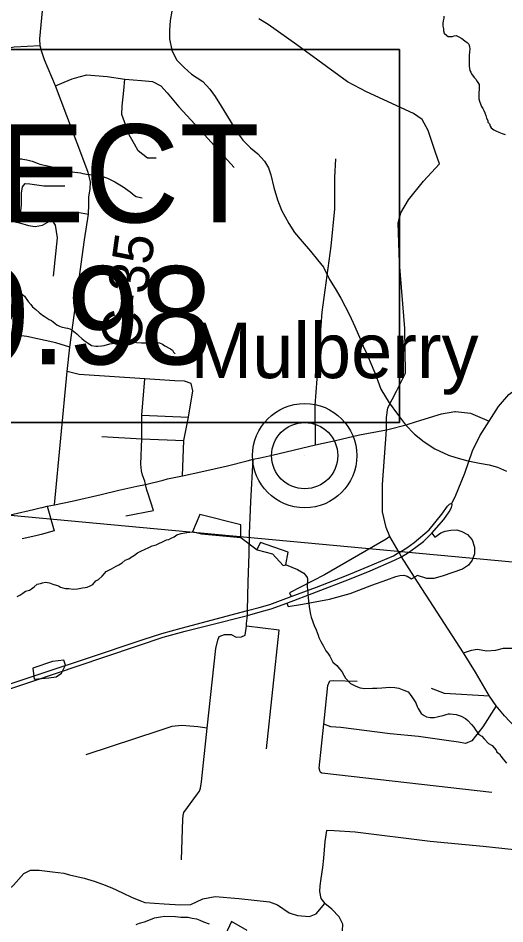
# Model space of a CAD drawing. Extents: x 44.2 to 78.2, y 4.5 to 26.5.
# Drawn here: x 51.721 to 52.415, y 22.487 to 23.779 of the extents above; entities that cross this region are included whole.
import ezdxf

# ---------------------------------------------------------------- set-up
doc = ezdxf.new("R2010")
doc.units = 0
for name, color, linetype in [('GM_X_County_Road', 7, 'Continuous'), ('GM_X_County_Road_Text', 7, 'Continuous'), ('GM_X_Interchange_Ramps', 7, 'Continuous'), ('GM_X_Minor_Lake', 7, 'Continuous'), ('GM_X_Minor_River', 7, 'Continuous'), ('GM_X_Rail_Line', 7, 'Continuous'), ('GM_X_State_Route', 7, 'Continuous'), ('GM_X_Township_Road', 7, 'Continuous'), ('GM_X_Unincorporated', 7, 'Continuous'), ('GM_X_Unincorporated_Location', 7, 'Continuous'), ('GM_X_Unincorporated_Text', 7, 'Continuous'), ('SH_Data', 7, 'Continuous')]:
    doc.layers.add(name, color=color, linetype=linetype)

msp = doc.modelspace()

# ---------------------------------------------------------------- linework, layer by layer
at = {"layer": 'GM_X_County_Road'}
for points in [[(51.7724, 23.0847), (51.7904, 23.275), (51.7942, 23.3094), (51.8152, 23.4625), (51.8209, 23.4995), (51.8212, 23.5132), (51.8215, 23.5242), (51.8231, 23.5348), (51.8237, 23.5452), (51.8206, 23.5586), (51.8127, 23.5793), (51.7739, 23.6823), (51.758, 23.7196), (51.7544, 23.7308), (51.7519, 23.7394), (51.7513, 23.7495), (51.7553, 23.7894)], [(52.2457, 23.1915), (52.2759, 23.1992), (52.2769, 23.1995), (52.2949, 23.2051), (52.3242, 23.2142), (52.3432, 23.2176)], [(52.3432, 23.2176), (52.3442, 23.2178), (52.3658, 23.2151), (52.392, 23.2039)], [(52.1445, 23.1699), (52.1732, 23.1765), (52.2075, 23.1844), (52.2457, 23.1915)], [(52.4297, 22.7666), (52.4143, 22.7834), (52.4023, 22.7977), (52.3929, 22.8113), (52.3729, 22.8456), (52.3558, 22.8733), (52.286, 22.9814), (52.2672, 23.0102), (52.2637, 23.0165), (52.2508, 23.0395), (52.2454, 23.0522), (52.2403, 23.0744), (52.2403, 23.1134), (52.2457, 23.1915)], [(52.0658, 23.1517), (52.0829, 23.1552), (52.1445, 23.1699)], [(51.9548, 23.1261), (51.9809, 23.1315), (52.0193, 23.1403), (52.047, 23.1472), (52.0558, 23.1496), (52.0658, 23.1517)], [(51.9335, 23.1214), (51.9357, 23.122), (51.9548, 23.1261)], [(51.752, 23.08), (51.7548, 23.0806), (51.7619, 23.0826), (51.7724, 23.0847), (51.7978, 23.0899), (51.8388, 23.0991), (51.8641, 23.1054), (51.8896, 23.1112), (51.9021, 23.1133), (51.9272, 23.1196), (51.9335, 23.1214)], [(51.4821, 22.9984), (51.5064, 23.006), (51.5755, 23.0285), (51.5867, 23.0313), (51.6084, 23.0392), (51.6492, 23.0535), (51.6529, 23.0548), (51.674, 23.0604), (51.6857, 23.0638), (51.697, 23.0668), (51.7135, 23.071), (51.7425, 23.0778), (51.752, 23.08)]]:
    msp.add_lwpolyline(points, dxfattribs=at)
at = {"layer": 'GM_X_Interchange_Ramps'}
for points in [[(52.3107, 23.0441), (52.3147, 23.0386), (52.3234, 23.0444), (52.3295, 23.0467), (52.3376, 23.0483), (52.3461, 23.0488), (52.3532, 23.0465), (52.3614, 23.0423), (52.3681, 23.0346), (52.3712, 23.0239), (52.3713, 23.0144), (52.3678, 23.0055), (52.3626, 22.9982), (52.3541, 22.9929), (52.325, 22.9828), (52.3135, 22.9793), (52.3032, 22.9795), (52.2901, 22.9835), (52.286, 22.9814)], [(52.2508, 23.0395), (52.2454, 23.0357), (52.1572, 22.9846), (52.1077, 22.9588), (52.1098, 22.9536)], [(52.1037, 22.9444), (52.1055, 22.9392), (52.1262, 22.9426), (52.1647, 22.95), (52.194, 22.958), (52.2251, 22.9698), (52.2464, 22.9774), (52.2591, 22.9822), (52.2649, 22.9839), (52.2705, 22.9841), (52.2754, 22.9826), (52.2817, 22.9788), (52.286, 22.9814)]]:
    msp.add_lwpolyline(points, dxfattribs=at)
at = {"layer": 'GM_X_Minor_Lake'}
for points in [[(51.9704, 23.0459), (51.9821, 23.0432), (52.0381, 23.0379), (52.0381, 23.0561), (51.9797, 23.0709), (51.9694, 23.0459)], [(52.0381, 23.0379), (52.0616, 23.0204), (52.0831, 23.0147), (52.0983, 22.9981), (52.1025, 22.9988), (52.1055, 23.0169)], [(52.1055, 23.0169), (52.0664, 23.0306), (52.061, 23.0209)], [(51.7417, 22.8515), (51.7433, 22.8355), (51.7642, 22.8378), (51.7748, 22.8391), (51.7825, 22.8442), (51.788, 22.8555), (51.7859, 22.8627), (51.7696, 22.8608)], [(51.7696, 22.8608), (51.7417, 22.8515)], [(52.0472, 22.4772), (52.025, 22.49), (52.0159, 22.4706)]]:
    msp.add_lwpolyline(points, dxfattribs=at)
at = {"layer": 'GM_X_Minor_River'}
for points in [[(51.9395, 23.7891), (51.9373, 23.7755), (51.9363, 23.7619), (51.9364, 23.7494), (51.9399, 23.7334), (51.9464, 23.7196), (51.9572, 23.7084), (51.968, 23.6991), (51.984, 23.6885), (51.9941, 23.6777), (52.0014, 23.6673), (52.0102, 23.6535), (52.0176, 23.6412), (52.0242, 23.6301), (52.0322, 23.617), (52.0411, 23.6047), (52.0518, 23.5939), (52.0623, 23.5854), (52.0719, 23.5749), (52.0778, 23.5653), (52.081, 23.5554), (52.0852, 23.5375), (52.0905, 23.5196), (52.0962, 23.5051), (52.1065, 23.4859), (52.1145, 23.4732), (52.1256, 23.4605), (52.1375, 23.4463), (52.1475, 23.4339), (52.156, 23.4235), (52.1647, 23.4059), (52.1728, 23.3932), (52.1805, 23.3794), (52.1867, 23.3676), (52.1932, 23.3557), (52.2005, 23.3389), (52.2088, 23.3205), (52.2128, 23.3109), (52.2179, 23.2999), (52.2226, 23.2884), (52.2291, 23.2731), (52.2334, 23.2616), (52.2377, 23.2494), (52.2498, 23.2302), (52.2616, 23.2137), (52.273, 23.1987), (52.2856, 23.1852), (52.2994, 23.1743), (52.3148, 23.1645), (52.3343, 23.1554), (52.3448, 23.1522), (52.3618, 23.1473), (52.3784, 23.1439), (52.392, 23.1418), (52.4041, 23.1381), (52.4168, 23.1326)], [(52.3278, 23.7818), (52.3274, 23.7788), (52.3265, 23.775), (52.326, 23.772), (52.3263, 23.7674), (52.327, 23.764), (52.3269, 23.761), (52.3283, 23.7575), (52.3317, 23.7544), (52.3339, 23.7528), (52.34, 23.7527), (52.3423, 23.7537), (52.3454, 23.7544), (52.3491, 23.7524), (52.3532, 23.75), (52.3573, 23.7465), (52.3611, 23.7445), (52.3633, 23.7418), (52.3643, 23.7384), (52.3646, 23.7349), (52.3641, 23.7308), (52.3636, 23.7255), (52.3635, 23.7217), (52.3638, 23.716), (52.3636, 23.7107), (52.3646, 23.7042), (52.3661, 23.7019), (52.3671, 23.6996)], [(52.3671, 23.6996), (52.3708, 23.6942), (52.3734, 23.6919), (52.3752, 23.6888), (52.3778, 23.6842), (52.3781, 23.6819), (52.378, 23.6769), (52.3775, 23.6732), (52.3777, 23.6663), (52.3776, 23.6637), (52.3783, 23.6606), (52.3804, 23.6553), (52.3811, 23.653), (52.383, 23.6503), (52.3848, 23.6472), (52.3862, 23.6441), (52.3877, 23.6399), (52.3883, 23.6361), (52.3901, 23.633), (52.3905, 23.6307), (52.3927, 23.6284), (52.3937, 23.6249), (52.3952, 23.6223), (52.3989, 23.6195), (52.4019, 23.6183), (52.406, 23.6163), (52.4106, 23.6143), (52.4151, 23.613)], [(51.7199, 23.5788), (51.7226, 23.5784), (51.7252, 23.5783), (51.7275, 23.5779), (51.7301, 23.5774), (51.7331, 23.577), (51.7407, 23.5749), (51.749, 23.5716)], [(51.749, 23.5716), (51.7516, 23.5708), (51.7539, 23.5704), (51.7576, 23.5691), (51.7607, 23.5687), (51.7667, 23.5674), (51.769, 23.5669), (51.7716, 23.5665), (51.7762, 23.5652), (51.7788, 23.564), (51.786, 23.5623), (51.789, 23.5615), (51.7943, 23.5602), (51.798, 23.5597), (51.8014, 23.5593), (51.8056, 23.5588), (51.8094, 23.5583), (51.8128, 23.5575), (51.8207, 23.5561), (51.823, 23.5557), (51.8283, 23.5548), (51.8313, 23.5543), (51.8347, 23.5538), (51.8374, 23.5534), (51.8415, 23.5529), (51.8453, 23.5517), (51.8479, 23.5505), (51.851, 23.5493), (51.8536, 23.5477), (51.8584, 23.5453), (51.8607, 23.5441), (51.8656, 23.5413), (51.8678, 23.5397), (51.8704, 23.5381), (51.8771, 23.5334), (51.8805, 23.531), (51.8831, 23.5287), (51.8864, 23.5259), (51.8891, 23.5247), (51.8951, 23.5231), (51.8974, 23.5226)], [(51.7182, 23.3908), (51.7223, 23.388), (51.7249, 23.3861), (51.7297, 23.3821), (51.7349, 23.3748), (51.7386, 23.3705), (51.7411, 23.3671), (51.7456, 23.3631), (51.7504, 23.3588), (51.7553, 23.3553), (51.7575, 23.3537), (51.7605, 23.3518), (51.7646, 23.349), (51.768, 23.3474), (51.7706, 23.3458), (51.7736, 23.3434), (51.7758, 23.3415), (51.7796, 23.3395), (51.7818, 23.3387), (51.7879, 23.337), (51.7909, 23.3366), (51.7943, 23.3357), (51.7976, 23.3337), (51.8021, 23.3306), (51.8044, 23.3286), (51.8073, 23.3259), (51.8114, 23.322), (51.8148, 23.3192), (51.8174, 23.3173), (51.8203, 23.3153), (51.8252, 23.3118), (51.8313, 23.3108), (51.8343, 23.3108), (51.8396, 23.3114), (51.8434, 23.312), (51.8511, 23.3141), (51.8545, 23.3148), (51.8576, 23.3151), (51.8602, 23.3154), (51.864, 23.3161), (51.8675, 23.316), (51.8705, 23.3163), (51.8735, 23.3162), (51.877, 23.3165), (51.8895, 23.3161), (51.8967, 23.3156), (51.91, 23.3156)], [(51.91, 23.3156), (51.9199, 23.3161), (51.9221, 23.3157), (51.9263, 23.314), (51.9296, 23.3113), (51.9379, 23.3069), (51.9405, 23.305), (51.9423, 23.3023), (51.9445, 23.2999)], [(51.8536, 22.9932), (51.8602, 22.9969), (51.864, 22.999), (51.869, 23.0019), (51.8733, 23.0056), (51.8783, 23.0074), (51.8818, 23.01), (51.8864, 23.0125), (51.8907, 23.0162), (51.8964, 23.0191), (51.9007, 23.0208), (51.9068, 23.0237), (51.9118, 23.0259), (51.9172, 23.0276), (51.9222, 23.0298), (51.9256, 23.0312), (51.9321, 23.0344), (51.9356, 23.0351), (51.9387, 23.0369), (51.9429, 23.0387), (51.9471, 23.0416), (51.9529, 23.0434), (51.9582, 23.0444), (51.9609, 23.045), (51.97, 23.0459), (51.9704, 23.0459)], [(52.1026, 22.999), (52.1191, 22.992), (52.1281, 22.9868), (52.1303, 22.9841), (52.1329, 22.9806), (52.1332, 22.9784), (52.1329, 22.9685), (52.1332, 22.9628), (52.1335, 22.9601), (52.1338, 22.9567), (52.134, 22.9518), (52.1349, 22.943), (52.1359, 22.9362), (52.1376, 22.9282), (52.1386, 22.924), (52.1425, 22.9125), (52.1454, 22.906), (52.1483, 22.8987), (52.1493, 22.8953), (52.1522, 22.8895), (52.1558, 22.8826), (52.1591, 22.8761), (52.162, 22.8726), (52.165, 22.8687), (52.1693, 22.8599), (52.1749, 22.8552), (52.179, 22.8505), (52.1823, 22.8466), (52.1855, 22.8405), (52.1874, 22.837), (52.1944, 22.8296), (52.1985, 22.8276), (52.2023, 22.8256), (52.2083, 22.8232), (52.2151, 22.8226), (52.2261, 22.8227), (52.2322, 22.823), (52.239, 22.8235), (52.2505, 22.8244), (52.2577, 22.8238), (52.2633, 22.8229), (52.2705, 22.8201), (52.2769, 22.8176), (52.2798, 22.8137), (52.282, 22.8107), (52.285, 22.8064), (52.2875, 22.8018), (52.2896, 22.7968), (52.2911, 22.7937), (52.2955, 22.7868), (52.2996, 22.784), (52.3029, 22.782), (52.3079, 22.7808), (52.3136, 22.781), (52.3181, 22.782), (52.322, 22.7831), (52.3265, 22.7841), (52.3308, 22.7851), (52.3342, 22.7862), (52.3365, 22.7861), (52.3452, 22.7851), (52.3523, 22.783)], [(51.7193, 22.9539), (51.7228, 22.9557), (51.7274, 22.9583), (51.7313, 22.9612), (51.7366, 22.9629), (51.7397, 22.9648), (51.7436, 22.9673), (51.7479, 22.9714), (51.7524, 22.9724), (51.7555, 22.9734), (51.7597, 22.9741), (51.7654, 22.9732), (51.7699, 22.9715), (51.7748, 22.9699), (51.7782, 22.9687), (51.7812, 22.9671), (51.7842, 22.9659), (51.7883, 22.965), (51.7929, 22.9649), (51.799, 22.9643), (51.8054, 22.9646), (51.8123, 22.9659), (51.8161, 22.9665), (51.8192, 22.9672), (51.8234, 22.969), (51.8269, 22.9708), (51.8312, 22.976), (51.8354, 22.9778), (51.8404, 22.9826), (51.8436, 22.9867), (51.8459, 22.9893), (51.8536, 22.9932)], [(52.3523, 22.783), (52.3583, 22.7795), (52.3617, 22.7767), (52.3669, 22.7709), (52.3702, 22.767), (52.3727, 22.7632), (52.3775, 22.757), (52.3816, 22.7542), (52.3853, 22.7507), (52.3913, 22.7441), (52.3965, 22.7409), (52.402, 22.7343), (52.4031, 22.7317), (52.4068, 22.7293), (52.409, 22.7258), (52.4123, 22.7216), (52.4171, 22.7161)], [(51.8891, 22.4857), (51.8937, 22.4875), (51.9006, 22.4896), (51.9067, 22.4917), (51.9148, 22.4953), (51.9235, 22.4966), (51.9296, 22.4976), (51.9452, 22.4972), (51.9524, 22.4962), (51.963, 22.4959), (51.9687, 22.4947), (51.9747, 22.4937), (51.9796, 22.4917), (51.9849, 22.4893), (51.9928, 22.4864)]]:
    msp.add_lwpolyline(points, dxfattribs=at)
at = {"layer": 'GM_X_Rail_Line'}
msp.add_lwpolyline([(53.1359, 22.9366), (51.7095, 23.0692), (51.3035, 22.9372), (51.2406, 22.8978), (51.1586, 22.8089), (51.1021, 22.7705), (50.546, 22.4779)], dxfattribs=at)
at = {"layer": 'GM_X_State_Route'}
for points in [[(52.392, 23.2039), (52.4055, 23.225), (52.4203, 23.2419), (52.4475, 23.2618), (52.4734, 23.2742)], [(52.339, 23.0869), (52.3439, 23.096), (52.3576, 23.1296), (52.3686, 23.1614), (52.379, 23.1831), (52.392, 23.2039)], [(51.5862, 22.7881), (51.7391, 22.8392), (51.8396, 22.8723), (51.8774, 22.8851), (51.899, 22.8923), (51.9253, 22.9007), (51.9529, 22.9086), (52.0477, 22.9335), (52.0642, 22.938), (52.0796, 22.9425), (52.1098, 22.9536), (52.1458, 22.9671), (52.1886, 22.9839), (52.2198, 22.9966), (52.2556, 23.0119), (52.2626, 23.0158), (52.2637, 23.0165), (52.2748, 23.0232), (52.2854, 23.0308), (52.3065, 23.0488), (52.3246, 23.071), (52.3327, 23.0826), (52.3356, 23.0856), (52.339, 23.0869)], [(52.3107, 23.0441), (52.3276, 23.0634), (52.335, 23.0743), (52.3384, 23.0805), (52.3394, 23.0845), (52.339, 23.0869)], [(51.5647, 22.7742), (51.7402, 22.8325), (51.8429, 22.8672), (51.892, 22.8836), (51.9274, 22.8955), (51.9586, 22.9043), (51.9929, 22.9126), (52.0477, 22.9264), (52.0659, 22.9318), (52.0814, 22.9363), (52.1037, 22.9444), (52.146, 22.9604), (52.1931, 22.9784), (52.2224, 22.9901), (52.2572, 23.0054), (52.2672, 23.0102), (52.277, 23.0165), (52.2877, 23.0239), (52.2984, 23.032), (52.3107, 23.0441)]]:
    msp.add_lwpolyline(points, dxfattribs=at)
at = {"layer": 'GM_X_Township_Road'}
for p, q in [((51.7942, 23.3094), (51.7744, 23.3156)), ((51.8971, 23.2123), (51.9633, 23.2096)), ((51.874, 23.0687), (51.9134, 23.0762))]:
    msp.add_line(p, q, dxfattribs=at)
for points in [[(51.7519, 23.7394), (51.7149, 23.7374), (51.7015, 23.7348), (51.6881, 23.7322), (51.682, 23.7313), (51.6744, 23.73), (51.6645, 23.7303), (51.6472, 23.7322), (51.6345, 23.7366), (51.6194, 23.741), (51.6103, 23.7425), (51.6013, 23.7442), (51.5923, 23.7449), (51.5828, 23.7456), (51.5738, 23.7459), (51.5585, 23.7457), (51.5494, 23.7482), (51.5468, 23.7498), (51.5402, 23.7539), (51.535, 23.7594), (51.5333, 23.7664), (51.5321, 23.7739), (51.5311, 23.7864)], [(52.2457, 23.1915), (52.246, 23.2093), (52.2478, 23.2228), (52.2603, 23.2469), (52.2728, 23.2726), (52.2721, 23.3363), (52.2644, 23.4297), (52.2626, 23.487), (52.2662, 23.5013), (52.277, 23.5199), (52.2984, 23.5465), (52.3213, 23.5709), (52.3158, 23.5874), (52.3052, 23.6187), (52.2969, 23.6344), (52.2841, 23.6431), (52.2171, 23.6741), (52.1901, 23.6882), (52.1179, 23.7409), (52.0773, 23.7699), (52.0637, 23.7781)], [(51.7739, 23.6823), (51.7861, 23.6876), (51.7974, 23.6923), (51.8074, 23.6954), (51.8184, 23.6979), (51.8475, 23.6957), (51.8728, 23.692), (51.8966, 23.6901), (51.9123, 23.6885), (51.9239, 23.6826), (51.9329, 23.6726), (51.9496, 23.6526), (51.9726, 23.6275), (52.0287, 23.5661)], [(51.9173, 23.5793), (51.9048, 23.5793), (51.8919, 23.5896), (51.8863, 23.599), (51.8791, 23.6125), (51.8722, 23.6309), (51.8685, 23.6416), (51.8688, 23.6535), (51.8713, 23.676), (51.8728, 23.692)], [(52.1445, 23.1699), (52.1439, 23.2264), (52.1542, 23.3593), (52.1667, 23.4535), (52.1724, 23.5071), (52.1724, 23.5516), (52.1736, 23.5784)], [(51.7224, 23.4868), (51.7252, 23.5128), (51.7254, 23.5293), (51.7269, 23.5382), (51.7305, 23.5429), (51.7372, 23.5427), (51.7572, 23.5399), (51.787, 23.5397)], [(51.5842, 23.5223), (51.5854, 23.5207), (51.5881, 23.5186), (51.6033, 23.5104), (51.6164, 23.5031), (51.6274, 23.4965), (51.643, 23.493), (51.6586, 23.4932), (51.6654, 23.4936), (51.6782, 23.4942), (51.7055, 23.4905), (51.7224, 23.4868), (51.7352, 23.4831), (51.745, 23.4819), (51.7553, 23.4834), (51.7686, 23.4913), (51.7845, 23.501), (51.788, 23.5012)], [(51.788, 23.5012), (51.7937, 23.5016), (51.8051, 23.502), (51.8209, 23.4995)], [(51.771, 23.4106), (51.7767, 23.4657), (51.7737, 23.4836), (51.7686, 23.4913)], [(51.7744, 23.3156), (51.733, 23.3249), (51.6887, 23.3303), (51.6705, 23.3337), (51.6532, 23.3375), (51.6365, 23.3445), (51.6142, 23.349), (51.5878, 23.3522), (51.5686, 23.3527), (51.5509, 23.3527), (51.535, 23.3513), (51.5117, 23.3499), (51.4935, 23.3436), (51.4835, 23.3386), (51.473, 23.3322), (51.4596, 23.3194), (51.4549, 23.3081), (51.4534, 23.2971), (51.4585, 23.2752), (51.4728, 23.2412)], [(51.9673, 23.2575), (51.9579, 23.2609), (51.9442, 23.2615), (51.9014, 23.2643), (51.8076, 23.2703), (51.7904, 23.275)], [(51.9047, 23.104), (51.9031, 23.1093), (51.9021, 23.1133), (51.901, 23.1181), (51.8978, 23.1268), (51.8964, 23.1329), (51.8954, 23.1424), (51.8969, 23.1785), (51.8971, 23.2123), (51.9014, 23.2643)], [(51.9548, 23.1261), (51.957, 23.1763), (51.9633, 23.2096), (51.9696, 23.2472), (51.9673, 23.2575)], [(51.84, 23.1819), (51.8969, 23.1785), (51.957, 23.1763)], [(52.0746, 22.7365), (52.0926, 22.9056), (52.0462, 22.9113), (52.0463, 22.9153), (52.0477, 22.9264), (52.0477, 22.9335), (52.0484, 22.9746), (52.0502, 23.014), (52.0505, 23.0435), (52.0514, 23.0662), (52.0523, 23.0886), (52.0558, 23.1496)], [(51.9134, 23.0762), (51.9056, 23.1014), (51.9047, 23.104)], [(51.7619, 23.0826), (51.7719, 23.0475), (51.7535, 23.0424)], [(51.7535, 23.0424), (51.7457, 23.0401), (51.7265, 23.0361)], [(52.3558, 22.8733), (52.3669, 22.877), (52.3749, 22.8784), (52.3888, 22.8764), (52.4017, 22.877), (52.4125, 22.8798), (52.426, 22.8798), (52.4368, 22.8758), (52.4488, 22.8755), (52.4539, 22.8832), (52.4579, 22.9032), (52.4618, 22.9312)], [(51.9537, 22.5778), (51.9554, 22.6361), (51.9558, 22.6414), (51.957, 22.6456), (51.9761, 22.672), (51.9792, 22.6757), (51.9804, 22.6803), (51.9819, 22.689), (51.9903, 22.766), (52.0027, 22.8794), (52.0054, 22.8915), (52.007, 22.8968), (52.0147, 22.8993), (52.0244, 22.8993), (52.0317, 22.8955), (52.0389, 22.8962), (52.0441, 22.8985), (52.0462, 22.9113)], [(52.1511, 22.7035), (52.15, 22.7088), (52.1565, 22.7716), (52.1574, 22.7805), (52.1622, 22.8269), (52.1649, 22.8333)], [(52.1649, 22.8333), (52.1702, 22.8337), (52.2039, 22.8327)], [(52.3929, 22.8113), (52.3284, 22.8151), (52.3101, 22.8222)], [(52.4023, 22.7977), (52.3832, 22.7678), (52.3675, 22.7477), (52.3583, 22.7437), (52.3484, 22.7457), (52.3315, 22.7483), (52.2916, 22.7537), (52.2511, 22.7577), (52.1809, 22.7666), (52.1664, 22.7676), (52.1565, 22.7716)], [(51.9903, 22.766), (51.977, 22.7676), (51.9539, 22.7696), (51.9399, 22.7681), (51.9225, 22.7627), (51.8171, 22.7278)], [(52.1511, 22.7035), (52.1537, 22.7019), (52.3959, 22.6745)], [(52.4988, 22.5847), (52.3837, 22.5968), (52.308, 22.6043), (52.2013, 22.6172), (52.1711, 22.6194), (52.1605, 22.62), (52.1578, 22.6043), (52.1558, 22.5805), (52.1548, 22.567), (52.1522, 22.5511), (52.1506, 22.5409), (52.1505, 22.5329), (52.152, 22.5227), (52.158, 22.5156)], [(51.637, 22.4798), (51.6523, 22.491), (51.679, 22.512), (51.7022, 22.5308), (51.7138, 22.542), (51.7288, 22.5585), (51.7382, 22.563), (51.7505, 22.5634), (51.7697, 22.5608), (51.7858, 22.5589), (51.794, 22.5566), (51.8146, 22.5518), (51.8289, 22.5473), (51.8409, 22.5432), (51.8544, 22.5379), (51.8694, 22.5308), (51.8832, 22.524), (51.8965, 22.5188)], [(51.8965, 22.5188), (51.9012, 22.5169), (51.9286, 22.515), (51.9522, 22.5135), (51.967, 22.5141), (51.9841, 22.5225), (52.0017, 22.5255), (52.0354, 22.5229), (52.0789, 22.518), (52.0902, 22.5139), (52.107, 22.5023), (52.119, 22.4985), (52.1359, 22.497), (52.1454, 22.5007), (52.158, 22.5156)], [(52.1708, 22.3647), (52.1786, 22.4423), (52.1805, 22.4554), (52.182, 22.4706), (52.1829, 22.4764), (52.1835, 22.4862), (52.1783, 22.4967), (52.168, 22.5074), (52.158, 22.5156)]]:
    msp.add_lwpolyline(points, dxfattribs=at)
at = {"layer": 'GM_X_Unincorporated'}
for radius in [0.0744, 0.0472]:
    msp.add_circle((52.1292, 23.1547), radius, dxfattribs=at)
at = {"layer": 'GM_X_Unincorporated_Location'}
msp.add_line((52.1292, 23.1547), (52.1292, 23.1547), dxfattribs=at)
at = {"layer": 'SH_Data'}
msp.add_line((50.6141, 23.202), (52.2645, 23.202), dxfattribs=at)
msp.add_lwpolyline([(50.6141, 23.7345), (52.2645, 23.7345), (52.2645, 23.202), (50.6141, 23.202)], close=True, dxfattribs=at)
msp.add_lwpolyline([(52.2645, 23.202), (52.2645, 23.7345), (50.6141, 23.7345), (50.6141, 23.202)], dxfattribs=at)

# ---------------------------------------------------------------- texts
at = {"layer": 'GM_X_County_Road_Text'}
msp.add_text('C-35', height=0.05682, rotation=82.1108, dxfattribs=at).set_placement((51.8933, 23.3043))
at = {"layer": 'GM_X_Unincorporated_Text'}
msp.add_text('Mulberry', height=0.07898, rotation=0, dxfattribs=at).set_placement((51.9664, 23.2653))
at = {"layer": 'SH_Data'}
for s, p in [('END PROJECT', (50.7438, 23.4875)), ('STA. 33+19.98', (50.7438, 23.285))]:
    msp.add_text(s, height=0.14, dxfattribs=at).set_placement(p)

doc.saveas('drawing.dxf')
